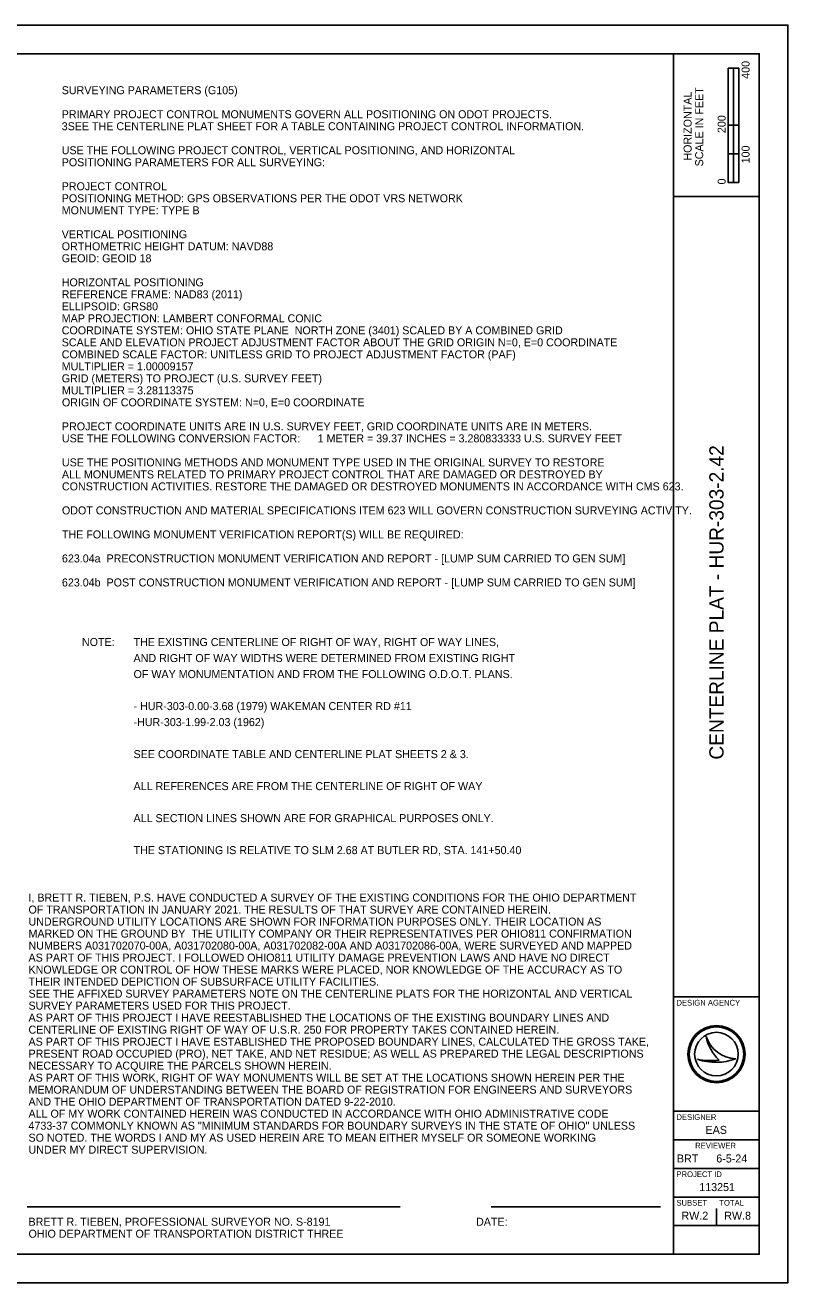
# Model space of a CAD drawing. Extents: x 2002808 to 2009608, y 570161 to 574561.
# Drawn here: x 2006938 to 2009608, y 570161 to 574561 of the extents above; entities that cross this region are included whole.
import ezdxf

# ---------------------------------------------------------------- set-up
doc = ezdxf.new("R2010")
doc.units = 0
for name, color, linetype in [('_CIVIL_CONSTRUCTION', 7, 'Continuous'), ('Default', 7, 'Continuous'), ('GE_P_Alignment', 7, 'Continuous'), ('GE_P_Alignment_100_Bearings', 7, 'Continuous'), ('SH_Text', 7, 'Continuous')]:
    doc.layers.add(name, color=color, linetype=linetype)

msp = doc.modelspace()

# ---------------------------------------------------------------- linework, layer by layer
at = {"layer": '_CIVIL_CONSTRUCTION'}
msp.add_lwpolyline([(2002808.2, 570161.3), (2009608.2, 570161.3), (2009608.2, 574561.3), (2002808.2, 574561.3)], close=True, dxfattribs=at)
at = {"layer": 'Default'}
for p, q in [((2006945.1, 570426.9), (2008250.7, 570426.9)), ((2008569.5, 570426.6), (2009162.4, 570426.6))]:
    msp.add_line(p, q, dxfattribs=at)
at = {"layer": 'GE_P_Alignment'}
for p, q in [((2009399.5, 574011.3), (2009399.5, 574411.3)), ((2009437, 574411.3), (2009399.5, 574411.3)), ((2009399.5, 574211.3), (2009399.5, 574411.3)), ((2009399.5, 574411.3), (2009418.2, 574411.3)), ((2009418.2, 574411.3), (2009418.3, 574411.3)), ((2009418.3, 574411.3), (2009418.3, 574211.3)), ((2009437, 574411.3), (2009437, 574011.3)), ((2009418.3, 574211.3), (2009399.5, 574211.3)), ((2009436.8, 574211.3), (2009418.2, 574211.3)), ((2009418.2, 574211.3), (2009418.2, 574111.3)), ((2009436.8, 574111.3), (2009436.8, 574211.3)), ((2009418.2, 574111.3), (2009399.5, 574111.3)), ((2009399.5, 574111.3), (2009399.5, 574011.3)), ((2009418.2, 574111.3), (2009436.8, 574111.3)), ((2009418.2, 574011.3), (2009418.2, 574111.3)), ((2009437, 574011.3), (2009399.5, 574011.3)), ((2009399.5, 574011.3), (2009418.2, 574011.3)), ((2009321.7, 571023.2), (2009321.7, 571023.2)), ((2009358.2, 570961.3), (2009358.2, 570961.3)), ((2009425.6, 570945), (2009425.6, 570945)), ((2009291.6, 570943.2), (2009291.6, 570943.2)), ((2009358.2, 570361.3), (2009358.2, 570421.3))]:
    msp.add_line(p, q, dxfattribs=at)
for radius in [100, 95.4, 95.4, 76.4]:
    msp.add_circle((2009358.2, 570961.3), radius, dxfattribs=at)
for centre, radius, start, end in [((2009431.4, 571060.8), 116, 198.9257, 198.9319), ((2009477.5, 571055.3), 159.1, 191.6379, 191.6421), ((2009431.4, 571060.8), 116, 198.9319, 267.1657), ((2009477.5, 571055.3), 159.1, 191.6421, 226.0947), ((2009356, 571135.3), 202.6, 251.4576, 290.0832), ((2009337.8, 571192.1), 253.2, 259.4964, 259.4995), ((2009356, 571135.3), 202.6, 251.4527, 251.4576), ((2009337.8, 571192.1), 253.2, 259.4995, 276.6672)]:
    msp.add_arc(centre, radius, start, end, dxfattribs=at)
at = {"layer": 'GE_P_Alignment_100_Bearings'}
for p, q in [((2009208.2, 570261.3), (2009208.2, 574461.3)), ((2009208.2, 573961.3), (2009508.2, 573961.3)), ((2009208.2, 571161.3), (2009508.2, 571161.3)), ((2009208.2, 570761.3), (2009508.2, 570761.3)), ((2009208.2, 570661.3), (2009508.2, 570661.3)), ((2009208.2, 570561.3), (2009508.2, 570561.3)), ((2009208.2, 570461.3), (2009508.2, 570461.3)), ((2009208.2, 570361.3), (2009508.2, 570361.3))]:
    msp.add_line(p, q, dxfattribs=at)
msp.add_lwpolyline([(2003108.2, 574461.3), (2009508.2, 574461.3), (2009508.2, 570261.3), (2003108.2, 570261.3)], close=True, dxfattribs=at)

# ---------------------------------------------------------------- texts
at = {"layer": 'Default'}
for s, p in [('I, BRETT R. TIEBEN, P.S. HAVE CONDUCTED A SURVEY OF THE EXISTING CONDITIONS FOR THE OHIO DEPARTMENT', (2006949.9, 571495.1)), ('OF TRANSPORTATION IN JANUARY 2021. THE RESULTS OF THAT SURVEY ARE CONTAINED HEREIN.', (2006949.9, 571453.1)), ('UNDERGROUND UTILITY LOCATIONS ARE SHOWN FOR INFORMATION PURPOSES ONLY. THEIR LOCATION AS', (2006949.9, 571411.1)), ('MARKED ON THE GROUND BY  THE UTILITY COMPANY OR THEIR REPRESENTATIVES PER OHIO811 CONFIRMATION', (2006949.9, 571369.1)), ('NUMBERS A031702070-00A, A031702080-00A, A031702082-00A AND A031702086-00A, WERE SURVEYED AND MAPPED', (2006949.9, 571327.1)), ('AS PART OF THIS PROJECT. I FOLLOWED OHIO811 UTILITY DAMAGE PREVENTION LAWS AND HAVE NO DIRECT', (2006949.9, 571285.1)), ('KNOWLEDGE OR CONTROL OF HOW THESE MARKS WERE PLACED, NOR KNOWLEDGE OF THE ACCURACY AS TO', (2006949.9, 571243.1)), ('THEIR INTENDED DEPICTION OF SUBSURFACE UTILITY FACILITIES.', (2006949.9, 571201.1)), ('SEE THE AFFIXED SURVEY PARAMETERS NOTE ON THE CENTERLINE PLATS FOR THE HORIZONTAL AND VERTICAL', (2006949.9, 571159.1)), ('SURVEY PARAMETERS USED FOR THIS PROJECT.', (2006949.9, 571117.1)), ('AS PART OF THIS PROJECT I HAVE REESTABLISHED THE LOCATIONS OF THE EXISTING BOUNDARY LINES AND', (2006949.9, 571075.1)), ('CENTERLINE OF EXISTING RIGHT OF WAY OF U.S.R. 250 FOR PROPERTY TAKES CONTAINED HEREIN.', (2006949.9, 571033.1)), ('AS PART OF THIS PROJECT I HAVE ESTABLISHED THE PROPOSED BOUNDARY LINES, CALCULATED THE GROSS TAKE,', (2006949.9, 570991.1)), ('PRESENT ROAD OCCUPIED (PRO), NET TAKE, AND NET RESIDUE; AS WELL AS PREPARED THE LEGAL DESCRIPTIONS', (2006949.9, 570949.1)), ('NECESSARY TO ACQUIRE THE PARCELS SHOWN HEREIN.', (2006949.9, 570907.1)), ('AS PART OF THIS WORK, RIGHT OF WAY MONUMENTS WILL BE SET AT THE LOCATIONS SHOWN HEREIN PER THE', (2006949.9, 570865.1)), ('MEMORANDUM OF UNDERSTANDING BETWEEN THE BOARD OF REGISTRATION FOR ENGINEERS AND SURVEYORS', (2006949.9, 570823.1)), ('AND THE OHIO DEPARTMENT OF TRANSPORTATION DATED 9-22-2010.', (2006949.9, 570781.1)), ('ALL OF MY WORK CONTAINED HEREIN WAS CONDUCTED IN ACCORDANCE WITH OHIO ADMINISTRATIVE CODE', (2006949.9, 570739.1)), ('4733-37 COMMONLY KNOWN AS "MINIMUM STANDARDS FOR BOUNDARY SURVEYS IN THE STATE OF OHIO" UNLESS', (2006949.9, 570697.1)), ('SO NOTED. THE WORDS I AND MY AS USED HEREIN ARE TO MEAN EITHER MYSELF OR SOMEONE WORKING', (2006949.9, 570655.1)), ('UNDER MY DIRECT SUPERVISION.', (2006949.9, 570613.1)), ('BRETT R. TIEBEN, PROFESSIONAL SURVEYOR NO. S-8191                                                 DATE:', (2006949.9, 570361.1)), ('OHIO DEPARTMENT OF TRANSPORTATION DISTRICT THREE', (2006949.9, 570319.1))]:
    msp.add_text(s, height=28, dxfattribs=at).set_placement(p)
at = {"layer": 'GE_P_Alignment'}
for s, height, p in [('400', 28, (2009474.2, 574373.6)), ('SCALE IN FEET', 28, (2009311.7, 574067.1)), ('HORIZONTAL', 28, (2009271.2, 574087.3)), ('200', 28, (2009390.3, 574183.6)), ('100', 28, (2009474.2, 574077.7)), ('0', 28, (2009390.3, 574004)), ('CENTERLINE PLAT - HUR-303-2.42', 50, (2009383.2, 571991.8))]:
    msp.add_text(s, height=height, rotation=90, dxfattribs=at).set_placement(p)
for s, height, p in [('DESIGN AGENCY', 20, (2009218.2, 571131.3)), ('DESIGNER', 20, (2009218.2, 570731.3)), ('EAS', 28, (2009320, 570682.3)), ('REVIEWER', 20, (2009283.8, 570631.3)), ('BRT', 28, (2009219.8, 570582.3)), ('6-5-24', 28, (2009357.6, 570582.3)), ('PROJECT ID', 20, (2009218.2, 570531.3)), ('113251', 28, (2009298, 570482.3)), ('SUBSET', 20, (2009218.2, 570431.3)), ('TOTAL', 20, (2009368.2, 570431.3)), ('RW.2', 28, (2009235.7, 570382.3)), ('RW.8', 28, (2009385.5, 570382.3))]:
    msp.add_text(s, height=height, dxfattribs=at).set_placement(p)
at = {"layer": 'SH_Text'}
for s, p in [('SURVEYING PARAMETERS (G105)', (2007066.2, 574319.6)), ('PRIMARY PROJECT CONTROL MONUMENTS GOVERN ALL POSITIONING ON ODOT PROJECTS.', (2007066.2, 574235.6)), ('3SEE THE CENTERLINE PLAT SHEET FOR A TABLE CONTAINING PROJECT CONTROL INFORMATION.', (2007066.2, 574193.6)), ('USE THE FOLLOWING PROJECT CONTROL, VERTICAL POSITIONING, AND HORIZONTAL', (2007066.2, 574109.6)), ('POSITIONING PARAMETERS FOR ALL SURVEYING:', (2007066.2, 574067.6)), ('PROJECT CONTROL', (2007066.2, 573983.6)), ('POSITIONING METHOD: GPS OBSERVATIONS PER THE ODOT VRS NETWORK', (2007066.2, 573941.6)), ('MONUMENT TYPE: TYPE B', (2007066.2, 573899.6)), ('VERTICAL POSITIONING', (2007066.2, 573815.6)), ('ORTHOMETRIC HEIGHT DATUM: NAVD88', (2007066.2, 573773.6)), ('GEOID: GEOID 18', (2007066.2, 573731.6)), ('HORIZONTAL POSITIONING', (2007066.2, 573647.6)), ('REFERENCE FRAME: NAD83 (2011)', (2007066.2, 573605.6)), ('ELLIPSOID: GRS80', (2007066.2, 573563.6)), ('MAP PROJECTION: LAMBERT CONFORMAL CONIC', (2007066.2, 573521.6)), ('COORDINATE SYSTEM: OHIO STATE PLANE  NORTH ZONE (3401) SCALED BY A COMBINED GRID', (2007066.2, 573479.6)), ('SCALE AND ELEVATION PROJECT ADJUSTMENT FACTOR ABOUT THE GRID ORIGIN N=0, E=0 COORDINATE', (2007066.2, 573437.6)), ('COMBINED SCALE FACTOR: UNITLESS GRID TO PROJECT ADJUSTMENT FACTOR (PAF)', (2007066.2, 573395.6)), ('MULTIPLIER = 1.00009157', (2007066.2, 573353.6)), ('GRID (METERS) TO PROJECT (U.S. SURVEY FEET) ', (2007066.2, 573311.6)), ('MULTIPLIER = 3.28113375', (2007066.9, 573269.6)), ('ORIGIN OF COORDINATE SYSTEM: N=0, E=0 COORDINATE', (2007066.9, 573227.6)), ('PROJECT COORDINATE UNITS ARE IN U.S. SURVEY FEET, GRID COORDINATE UNITS ARE IN METERS.', (2007066.9, 573143.6)), ('USE THE FOLLOWING CONVERSION FACTOR: ', (2007066.9, 573101.6)), ('1 METER = 39.37 INCHES = 3.280833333 U.S. SURVEY FEET', (2007962.2, 573101.6)), ('USE THE POSITIONING METHODS AND MONUMENT TYPE USED IN THE ORIGINAL SURVEY TO RESTORE', (2007066.9, 573017.6)), ('ALL MONUMENTS RELATED TO PRIMARY PROJECT CONTROL THAT ARE DAMAGED OR DESTROYED BY', (2007066.9, 572975.6)), ('CONSTRUCTION ACTIVITIES. RESTORE THE DAMAGED OR DESTROYED MONUMENTS IN ACCORDANCE WITH CMS 623.', (2007066.9, 572933.6)), ('ODOT CONSTRUCTION AND MATERIAL SPECIFICATIONS ITEM 623 WILL GOVERN CONSTRUCTION SURVEYING ACTIVITY.', (2007066.9, 572849.6)), ('THE FOLLOWING MONUMENT VERIFICATION REPORT(S) WILL BE REQUIRED:', (2007066.9, 572765.6)), ('623.04a  PRECONSTRUCTION MONUMENT VERIFICATION AND REPORT - [LUMP SUM CARRIED TO GEN SUM]', (2007066.9, 572681.6)), ('623.04b  POST CONSTRUCTION MONUMENT VERIFICATION AND REPORT - [LUMP SUM CARRIED TO GEN SUM]', (2007066.9, 572597.6)), ('NOTE:', (2007137, 572389.3)), ('THE EXISTING CENTERLINE OF RIGHT OF WAY, RIGHT OF WAY LINES,', (2007317.6, 572389)), ('AND RIGHT OF WAY WIDTHS WERE DETERMINED FROM EXISTING RIGHT', (2007317.6, 572333)), ('OF WAY MONUMENTATION AND FROM THE FOLLOWING O.D.O.T. PLANS.', (2007317.6, 572277)), ('- HUR-303-0.00-3.68 (1979) WAKEMAN CENTER RD #11', (2007317.6, 572165)), ('-HUR-303-1.99-2.03 (1962)', (2007317.6, 572109)), ('SEE COORDINATE TABLE AND CENTERLINE PLAT SHEETS 2 & 3.', (2007317.6, 571997)), ('ALL REFERENCES ARE FROM THE CENTERLINE OF RIGHT OF WAY', (2007317.6, 571885)), ('ALL SECTION LINES SHOWN ARE FOR GRAPHICAL PURPOSES ONLY.', (2007317.6, 571773)), ('THE STATIONING IS RELATIVE TO SLM 2.68 AT BUTLER RD, STA. 141+50.40', (2007317.6, 571661))]:
    msp.add_text(s, height=28, dxfattribs=at).set_placement(p)

doc.saveas('drawing.dxf')
